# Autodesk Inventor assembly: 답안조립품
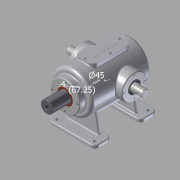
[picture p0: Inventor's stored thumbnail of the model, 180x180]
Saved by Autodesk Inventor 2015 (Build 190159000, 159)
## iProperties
Created: 2016-02
Part Number: 답안조립품
Document SubType Name: Assembly
Designer: Administrator
Author: Administrator
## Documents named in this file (15)
- C:\Users\Administrator\Desktop\360220V1018\답안조립품.iam
- C:\Users\Administrator\Desktop\360220V1018\본체.ipt
- C:\Users\Administrator\Desktop\360220V1018\슬라이드 커버.ipt
- C:\Users\Administrator\Desktop\360220V1018\축 커버.ipt
- C:\Users\Administrator\Desktop\360220V1018\상부커버.ipt
- C:\Users\Administrator\Desktop\360220V1018\볼트 M4x0.7.ipt
- C:\Users\Administrator\Desktop\360220V1018\육각머리볼트 M4.ipt
- C:\Users\Administrator\Desktop\360220V1018\오일실.ipt
- 오일실.ipt
- C:\Users\Administrator\Desktop\360220V1018\베어링 6205.ipt
- 베어링 6205.ipt
- C:\Users\Administrator\Desktop\360220V1018\편심축.ipt
- C:\Users\Administrator\Desktop\360220V1018\부시.ipt
- C:\Users\Administrator\Desktop\360220V1018\가변스프링.ipt
- C:\Users\Administrator\Desktop\360220V1018\슬라이드.ipt
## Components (13 placed, 2 different names)
1. 가변스프링:1
2. M4x0.7:1
3. M4x0.7:2
4. M4x0.7:3
5. M4x0.7:4
6. M4x0.7:5
7. M4x0.7:6
8. M4x0.7:7
9. M4x0.7:8
10. M4x0.7:9
11. M4x0.7:10
12. M4x0.7:11
13. M4x0.7:12
